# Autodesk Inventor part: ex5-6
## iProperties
Created: 2006-03
Part Number: ex5-6
Document SubType Name: Modeling
Designer: Elise Moss
Author: Elise Moss
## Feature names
1. Extrusion1
2. Hole1
3. Shell1
